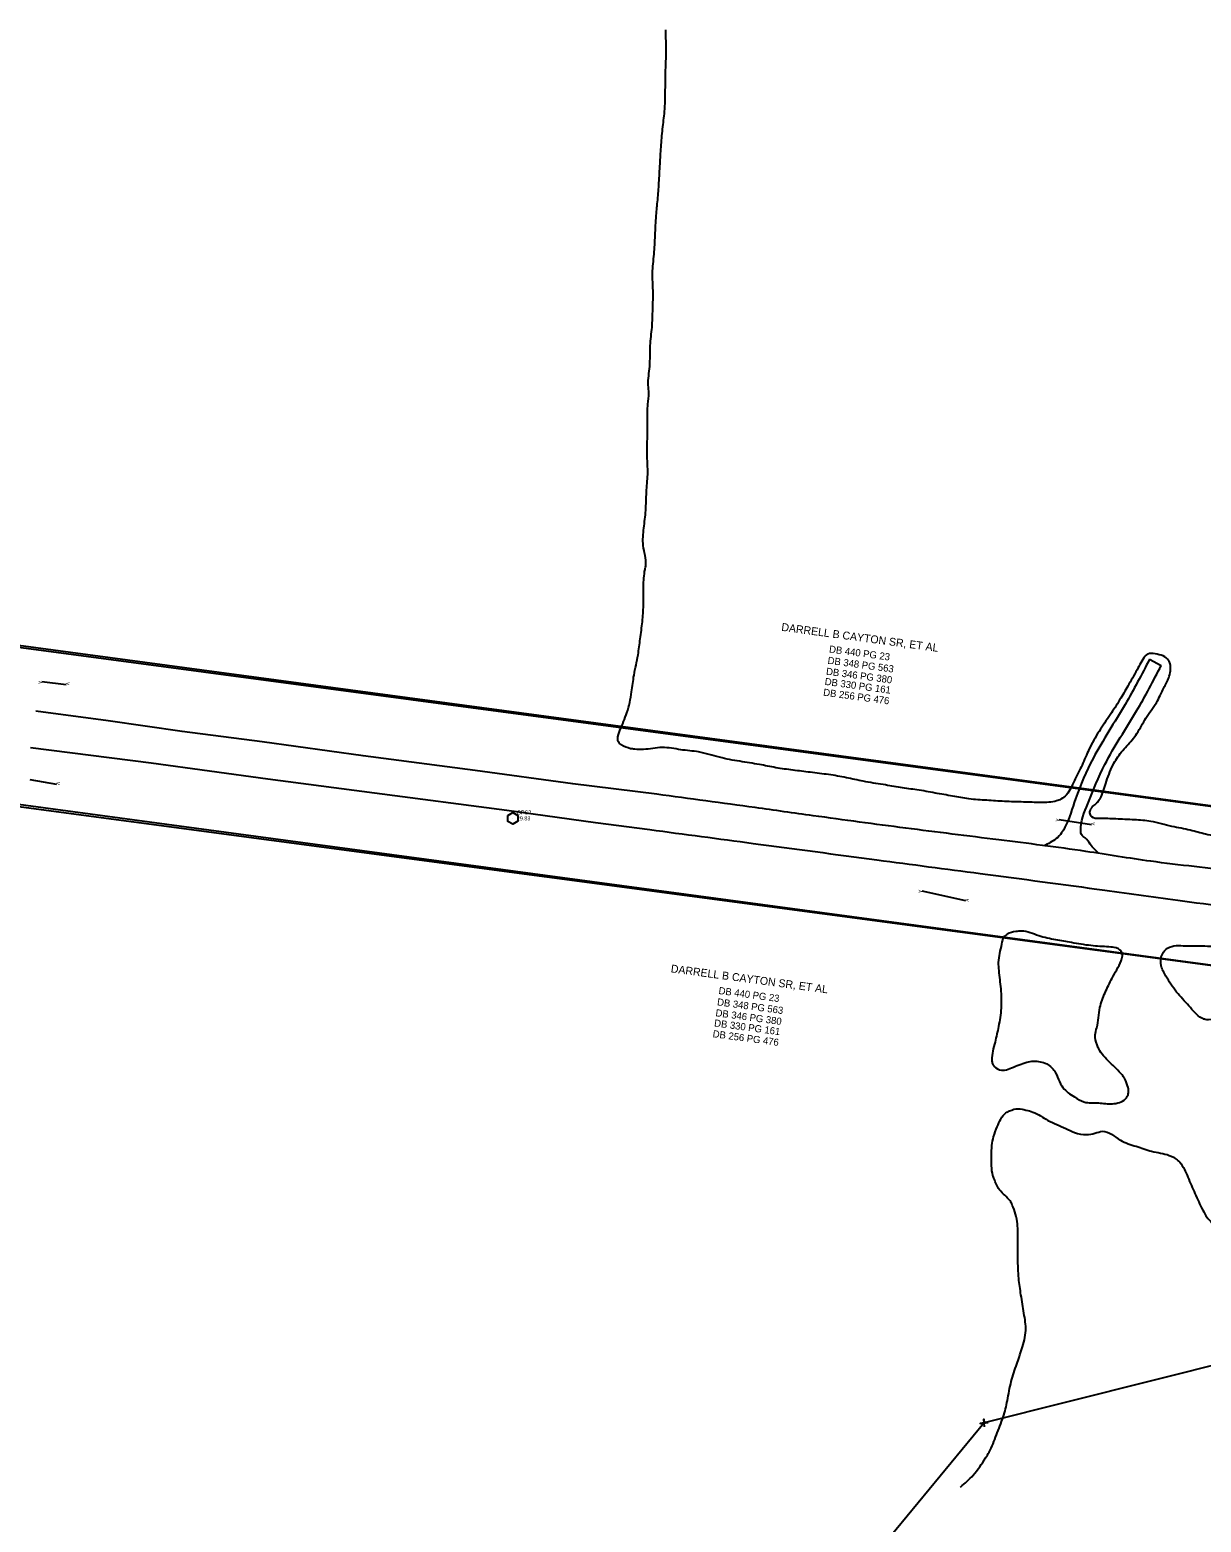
# Model space of a CAD drawing. Extents: x 2627243 to 2636458, y 566398 to 571062.
# Drawn here: x 2632963 to 2633704, y 568819 to 569764 of the extents above; entities that cross this region are included whole.
import ezdxf

# ---------------------------------------------------------------- set-up
doc = ezdxf.new("R2010")
doc.units = 0
for name, color, linetype in [('CTL GPS Vertical CELL', 7, 'Continuous'), ('CTL GPS Vertical Cogo Elevation', 7, 'Continuous'), ('CTL GPS Vertical Cogo Number', 7, 'Continuous'), ('Default', 7, 'Continuous'), ('Exist Property Corner CELL', 7, 'Continuous'), ('Exist Property Deed Book Text', 7, 'Continuous'), ('Exist Property Line', 7, 'Continuous'), ('Exist Property Owner Text', 7, 'Continuous'), ('Exist Right of Way Line', 7, 'Continuous'), ('Exist Roads EOP', 7, 'Continuous'), ('Exist Roads Soil', 7, 'Continuous'), ('Exist Structure Minor Culvert Topo', 7, 'Continuous'), ('Exist Vegetation Woods Line', 7, 'Continuous')]:
    doc.layers.add(name, color=color, linetype=linetype)

# ---------------------------------------------------------------- blocks, each defined once
blk = doc.blocks.new('CTL GPS VERTICAL')
at = {"layer": 'CTL GPS Vertical CELL'}
blk.add_line((-0.001, 0), (-0.001, 0), dxfattribs=at)
blk.add_lwpolyline([(-0.065, 0.037), (0, 0.074), (0.065, 0.038), (0.064, -0.036), (-0.001, -0.074), (-0.065, -0.038)], close=True, dxfattribs=at)

msp = doc.modelspace()

# ---------------------------------------------------------------- linework, layer by layer
at = {"layer": 'Default'}
for p, q in [((2634079.46, 569223.09), (2632340.39, 569455.12)), ((2634066.1, 569123.99), (2632327.14, 569356))]:
    msp.add_line(p, q, dxfattribs=at)
at = {"layer": 'Exist Property Corner CELL'}
msp.add_line((2633567.02, 568881.75), (2633567.02, 568881.75), dxfattribs=at)
msp.add_lwpolyline([(2633567.26, 568879.26), (2633566.78, 568884.24), (2633567.02, 568881.75), (2633564.53, 568881.51), (2633569.51, 568881.98)], dxfattribs=at)
at = {"layer": 'Exist Property Line'}
for p, q in [((2634368.67, 569083.2), (2633567.02, 568881.75)), ((2633567.02, 568881.75), (2633293.08, 568550.06))]:
    msp.add_line(p, q, dxfattribs=at)
at = {"layer": 'Exist Right of Way Line'}
for p, q in [((2632427.74, 569445.76), (2634879.42, 569115.25)), ((2632403.14, 569348.18), (2634866.06, 569016.15))]:
    msp.add_line(p, q, dxfattribs=at)
at = {"layer": 'Exist Roads EOP'}
for points in [[(2633359.61, 569280.12), (2633306.49, 569286.79), (2633244.53, 569295.16), (2633173.76, 569304.38), (2633109.71, 569313.24), (2633059.02, 569319.86), (2633012.2, 569326.63), (2632966.37, 569332.69)], [(2632963, 569309.81), (2633039.48, 569299.98), (2633113.34, 569289.87), (2633180.85, 569281), (2633264.72, 569270.09), (2633320.91, 569262.09), (2633355.17, 569257.72)]]:
    msp.add_lwpolyline(points, dxfattribs=at)
for points in [[(2634098.59, 569180.52), (2634055.19, 569186.83), (2634006.66, 569193.66), (2633945.69, 569201.68), (2633886.74, 569209.43), (2633837.19, 569216.44), (2633775.43, 569224.58), (2633727.52, 569231.08), (2633672.51, 569237.63), (2633631.34, 569243.87), (2633576.25, 569251.19), (2633517.3, 569258.62), (2633458.69, 569266.49), (2633421.91, 569271.61), (2633359.61, 569280.12)], [(2633355.17, 569257.72), (2633420.69, 569248.98), (2633499.09, 569238.53), (2633564.45, 569229.89), (2633643.33, 569219.33), (2633692.63, 569212.56), (2633763.68, 569203.52), (2633830.49, 569194.37), (2633898.86, 569185.17), (2633968.75, 569175.7), (2634042.6, 569166.27), (2634090.06, 569160.3)]]:
    msp.add_spline(points, degree=3, dxfattribs=at)
at = {"layer": 'Exist Roads Soil'}
msp.add_line((2633671.77, 569365.62), (2633679.12, 569361.64), dxfattribs=at)
for points in [[(2633671.77, 569365.62), (2633656.26, 569337.01), (2633635.99, 569302.78), (2633624.84, 569277.23), (2633618.08, 569259.13), (2633616.05, 569255.69), (2633612.56, 569251.95), (2633608.86, 569249.52), (2633604.94, 569247.38)], [(2633639.68, 569242.6), (2633634.2, 569248.38), (2633630.95, 569252.38), (2633628.6, 569254.49), (2633628.17, 569256.76), (2633632.59, 569274.09), (2633643.44, 569298.97), (2633663.53, 569332.89), (2633679.12, 569361.64)]]:
    msp.add_spline(points, degree=3, dxfattribs=at)
at = {"layer": 'Exist Structure Minor Culvert Topo'}
for points in [[(2632970.05, 569351.44), (2632985.6, 569349.7)], [(2632962.61, 569289.36), (2632979.38, 569286.55)], [(2633614.48, 569264.11), (2633634.91, 569260.99)], [(2633527.46, 569218.89), (2633555.14, 569212.75)]]:
    msp.add_lwpolyline(points, dxfattribs=at)
at = {"layer": 'Exist Vegetation Woods Line'}
for points in [[(2633342.96, 569308.97), (2633337.1, 569311.43), (2633335.37, 569313.21), (2633334.94, 569315.19), (2633336.28, 569320.55), (2633340.7, 569331.76), (2633343.68, 569344.92), (2633345.2, 569355.52), (2633347.74, 569368.41), (2633349.15, 569378.53), (2633350.49, 569389.43), (2633351.18, 569399.71), (2633351.24, 569411.65), (2633352.19, 569422.51), (2633352.7, 569425.29), (2633351.08, 569437.61), (2633351.46, 569448.72), (2633352.61, 569459.91), (2633353.1, 569471.5), (2633353.86, 569482.65), (2633353.53, 569496.19), (2633353.69, 569506.34), (2633353.67, 569516.79), (2633354.03, 569527.28), (2633354.59, 569534.2), (2633354.24, 569539.31), (2633355.16, 569551.18), (2633355.5, 569564.31), (2633356.61, 569575.89), (2633357.09, 569587.48), (2633357.25, 569599.27), (2633356.95, 569610.16), (2633357.93, 569622.27), (2633358.61, 569634.19), (2633359.32, 569646.74), (2633360.19, 569656.73), (2633361, 569667.49), (2633361.68, 569679.42), (2633362.34, 569690.09), (2633363.3, 569701.57), (2633364.55, 569712.61), (2633365.04, 569726.47), (2633365.18, 569737.63), (2633365.56, 569748.74), (2633365.42, 569760.35), (2633365.33, 569764.4)], [(2634085.09, 569207.09), (2634085.19, 569206.95), (2634075.25, 569208.06), (2634063.09, 569208.8), (2634050.79, 569210.08), (2634040.62, 569211.25), (2634029.19, 569212.45), (2634018.11, 569214.08), (2634012.97, 569214.74), (2634000.09, 569215.65), (2633989.45, 569217.55), (2633979.25, 569219.74), (2633967.55, 569221.38), (2633954.51, 569223.83), (2633942.69, 569226.63), (2633932.24, 569228.24), (2633919.76, 569229.81), (2633909.01, 569231.24), (2633898.3, 569232.28), (2633885.13, 569233), (2633872.69, 569234.18), (2633862.5, 569234.73), (2633852.08, 569235.95), (2633840.61, 569237.54), (2633823.31, 569240.58), (2633811.66, 569242.47), (2633797.6, 569244.27), (2633779.67, 569245.68), (2633768.29, 569246.5), (2633755.99, 569247.77), (2633744.97, 569249.64), (2633731.51, 569250.8), (2633719.24, 569252.7), (2633707.25, 569254.79), (2633697.5, 569257.25), (2633685.86, 569259.76), (2633672.6, 569262.88), (2633662.13, 569263.87), (2633650.3, 569264.41), (2633640.05, 569264.72), (2633635.12, 569265.71), (2633634.06, 569267.71), (2633634.22, 569270.07), (2633639.07, 569275.38), (2633640.37, 569277.23), (2633643.94, 569286.86), (2633648.62, 569298.64), (2633650.94, 569302.77), (2633657.4, 569310.74), (2633663.71, 569318.62), (2633669.45, 569328.39), (2633676.05, 569338.1), (2633680.81, 569347.46), (2633683.91, 569353.93), (2633684.89, 569358.24), (2633684.76, 569362.67), (2633683.76, 569364.91), (2633680.36, 569367.69), (2633675.24, 569368.98), (2633670.57, 569368.91), (2633668.99, 569367.5), (2633663.77, 569358.87), (2633657.92, 569348.62), (2633652.79, 569339.84), (2633646.78, 569330.51), (2633639.72, 569319.9), (2633633.36, 569308.51), (2633628.97, 569298.56), (2633624.1, 569288.71), (2633619.06, 569279.79), (2633615.52, 569276.94), (2633612.89, 569275.9), (2633602.86, 569274.9), (2633591.84, 569275.14), (2633579.86, 569275.58), (2633568.56, 569276.25), (2633557.32, 569277.16), (2633547.01, 569278.87), (2633535.89, 569280.88), (2633524.39, 569282.86), (2633514.03, 569284.33), (2633503, 569286.19), (2633490.39, 569288.29), (2633479.71, 569290.59), (2633468.45, 569292.51), (2633456.83, 569294.01), (2633445.94, 569295.34), (2633435.1, 569296.92), (2633424.6, 569298.91), (2633412.23, 569300.96), (2633399.35, 569303.5), (2633386.15, 569306.87), (2633374.77, 569308.31), (2633363.01, 569309.72), (2633351.28, 569308.47), (2633345.65, 569308.62), (2633342.96, 569308.97)], [(2633639.35, 569084.6), (2633630.17, 569085.17), (2633624.09, 569088.31), (2633616.87, 569094.22), (2633611.46, 569104.76), (2633609.59, 569107.07), (2633606.56, 569109.26), (2633602.46, 569110.57), (2633598.28, 569111.01), (2633593.98, 569110.35), (2633584.35, 569106.74), (2633579.89, 569105.36), (2633577.87, 569105.32), (2633573.35, 569107.6), (2633572.24, 569109.36), (2633571.86, 569111.58), (2633573.84, 569123.09), (2633576.06, 569132.9), (2633577.71, 569144.61), (2633577.43, 569156.75), (2633576.19, 569168.48), (2633575.93, 569173.45), (2633577.96, 569185.19), (2633579.47, 569189.63), (2633581.63, 569191.4), (2633586.93, 569193.1), (2633590.64, 569193.39), (2633601.54, 569190.42), (2633612.41, 569187.83), (2633622.33, 569186.09), (2633634.6, 569184.19), (2633645.99, 569183.37), (2633650.5, 569182.73), (2633652.55, 569181.76), (2633654.05, 569180.04), (2633654.52, 569177.67), (2633653.66, 569174.46), (2633648.04, 569163.53), (2633643.57, 569154.35), (2633640.3, 569144.9), (2633638.29, 569132.15), (2633637.26, 569127.6), (2633638.5, 569121.41), (2633639.54, 569118.78), (2633642.56, 569114.32), (2633650.78, 569106.17), (2633654.29, 569102.23), (2633655.83, 569100.12), (2633657.78, 569095.4), (2633658.38, 569090.86), (2633657.6, 569088.52), (2633656.36, 569086.91), (2633652.74, 569084.84), (2633648.15, 569083.99), (2633639.35, 569084.6)], [(2633916.75, 569129.48), (2633906.91, 569127.18), (2633904.3, 569126.76), (2633892.5, 569126.29), (2633880.46, 569126.5), (2633870.62, 569127.47), (2633857.9, 569129.09), (2633845.29, 569131.19), (2633835.33, 569133.32), (2633824.84, 569135.32), (2633813.5, 569136.38), (2633800.69, 569135.89), (2633796.25, 569135.76), (2633794.34, 569134.55), (2633792.9, 569132.62), (2633784.7, 569126.42), (2633780.9, 569124.64), (2633770.24, 569123.66), (2633758.15, 569123.63), (2633751.16, 569124.96), (2633748.98, 569126.46), (2633747.3, 569128.47), (2633744.71, 569134.85), (2633743.09, 569137.1), (2633732.63, 569138.71), (2633720.89, 569139.11), (2633709.15, 569137.24), (2633707.03, 569137.34), (2633704.84, 569138.21), (2633696.66, 569145.98), (2633688.84, 569154.8), (2633682.07, 569164.89), (2633679.15, 569171.46), (2633679.82, 569178.86), (2633683.19, 569182.62), (2633694.59, 569184.07), (2633706.77, 569183.95), (2633719.7, 569183.29), (2633732.16, 569181.1), (2633744.94, 569178.08), (2633756.1, 569175.68), (2633767.55, 569173.46), (2633780.2, 569170.97), (2633791.9, 569169.33), (2633804.38, 569167.76), (2633816.57, 569166.01), (2633827.01, 569166.03), (2633838.73, 569166.65), (2633852.27, 569166.98), (2633862.74, 569166), (2633872.71, 569164.49), (2633886.09, 569162.47), (2633898.24, 569161.1), (2633912.82, 569158.81), (2633927.33, 569155.65), (2633940.1, 569152.63), (2633950.85, 569151.2), (2633961.84, 569149.72), (2633973.43, 569149.23), (2633984.77, 569148.17), (2633997.52, 569146.17), (2634007.68, 569144.37), (2634014.11, 569143.29), (2634016.7, 569143.08), (2634019.06, 569142.93), (2634031.02, 569141.85), (2634033.61, 569141.64), (2634043.44, 569141.68), (2634053.59, 569141.52), (2634065.59, 569140.06), (2634077.51, 569139.38), (2634081.98, 569139.12), (2634088.42, 569138.67), (2634093.73, 569135.45), (2634093.87, 569134.75)], [(2633552.02, 568841.17), (2633560.01, 568848.67), (2633567.89, 568859.59), (2633570.1, 568863.24), (2633574.71, 568874.15), (2633579.04, 568885.5), (2633581.66, 568895.98), (2633584.14, 568908), (2633587.64, 568919.04), (2633590.82, 568928.63), (2633593.33, 568940.27), (2633592.16, 568951.23), (2633590.29, 568962.97), (2633588.87, 568973.36), (2633588.32, 568985.94), (2633588.32, 568997.01), (2633588.01, 569007.9), (2633584.8, 569019.83), (2633583.37, 569022.42), (2633576.67, 569029.47), (2633573.33, 569036.39), (2633572.56, 569038.58), (2633571.72, 569050.97), (2633571.84, 569057.61), (2633572.94, 569063.03), (2633575.27, 569069.42), (2633580.79, 569078.23), (2633583.09, 569079.48), (2633588.56, 569080.88), (2633593.4, 569080.03), (2633597.9, 569078.76), (2633607.39, 569073.47), (2633618.67, 569068.27), (2633624.14, 569065.78), (2633631.76, 569064.43), (2633637.13, 569065.35), (2633641.93, 569066.53), (2633653.25, 569060.95), (2633663.3, 569057.03), (2633673.05, 569053.95), (2633684.15, 569051.31), (2633689.18, 569048.53), (2633690.83, 569046.9), (2633695.98, 569037.43), (2633700.44, 569027.11), (2633705.37, 569016.68), (2633708.19, 569011.89), (2633713.03, 569007.15), (2633716.86, 569004.64), (2633727.49, 569000.47), (2633739.55, 568999.25), (2633742.49, 568999.47), (2633752.02, 568995.42), (2633762.69, 568990.87), (2633773.83, 568986.2), (2633778.24, 568983.45), (2633784.62, 568974.95), (2633788.32, 568970.72), (2633794.92, 568963.19), (2633803.13, 568952.77), (2633812.29, 568943.78), (2633820.15, 568936.84), (2633823.69, 568934.15), (2633830.35, 568930.76), (2633842.59, 568927.6), (2633845.79, 568928.39), (2633848.01, 568930.4), (2633849.81, 568935.03), (2633851.08, 568947.32), (2633850.06, 568960.01), (2633849.4, 568972.11), (2633850.28, 568974.3), (2633853.59, 568977.83), (2633865.06, 568984.04), (2633875.66, 568988.06), (2633887.17, 568993.88), (2633894.11, 568997.85), (2633897.9, 569001.26), (2633905.94, 569010.64), (2633913.35, 569020.04), (2633917.21, 569024.32), (2633925.41, 569030.52), (2633932.77, 569038.03), (2633935.19, 569042.02), (2633936.52, 569045.11), (2633939.24, 569057.7), (2633940.28, 569070.05), (2633940.65, 569081.16), (2633941.46, 569091.93), (2633943.01, 569103.78), (2633943.97, 569115.26), (2633943.75, 569121.48), (2633942.56, 569124.01), (2633937.46, 569128.19), (2633933.26, 569129.64), (2633925.77, 569130.46), (2633916.75, 569129.48)]]:
    msp.add_spline(points, degree=3, dxfattribs=at)

# ---------------------------------------------------------------- block references
at = {"layer": 'CTL GPS Vertical CELL', "xscale": 50, "yscale": 50}
msp.add_blockref('CTL GPS VERTICAL', (2633268.44, 569264.81), dxfattribs=at)

# ---------------------------------------------------------------- texts
at = {"layer": 'CTL GPS Vertical Cogo Elevation'}
msp.add_text('29.83', height=2.5, dxfattribs=at).set_placement((2633270.94, 569263.56))
at = {"layer": 'CTL GPS Vertical Cogo Number'}
msp.add_text('GPS2', height=2.5, dxfattribs=at).set_placement((2633270.94, 569267.31))
at = {"layer": 'Exist Property Deed Book Text'}
for s, p in [('DB 440 PG 23', (2633468.55, 569369.97)), ('DB 348 PG 563', (2633467.62, 569362.79)), ('DB 346 PG 380', (2633466.63, 569355.88)), ('DB 256 PG 476', (2633464.83, 569342.61)), ('DB 330 PG 161', (2633465.76, 569349.42)), ('DB 440 PG 23', (2633398.55, 569153.59)), ('DB 348 PG 563', (2633397.62, 569146.41)), ('DB 346 PG 380', (2633396.62, 569139.5)), ('DB 256 PG 476', (2633394.82, 569126.23)), ('DB 330 PG 161', (2633395.76, 569133.05))]:
    msp.add_text(s, height=4.5, rotation=352.32218, dxfattribs=at).set_placement(p)
at = {"layer": 'Exist Property Owner Text'}
for p in [(2633438.3, 569383.69), (2633368.29, 569167.31)]:
    msp.add_text('DARRELL B CAYTON SR, ET AL', height=5, rotation=352.32218, dxfattribs=at).set_placement(p)
at = {"layer": 'Exist Structure Minor Culvert Topo'}
for rotation, p in [(83.36931, (2632969.88, 569349.95)), (263.85101, (2632985.76, 569351.19)), (260.73159, (2632979.62, 569288.03)), (81.085, (2633614.24, 569262.63)), (261.56671, (2633635.13, 569262.48)), (77.24734, (2633527.13, 569217.43)), (257.72904, (2633555.46, 569214.22))]:
    msp.add_text('v', height=2.65, rotation=rotation, dxfattribs=at).set_placement(p)

doc.saveas('drawing.dxf')
